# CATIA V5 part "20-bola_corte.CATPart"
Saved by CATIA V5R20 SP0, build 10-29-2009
Part number: 20-bola_corte
Revision: ANY
Definition: UNKNOWN
Nomenclature: 20-bola_corte
Source: Unknown
Bounding box of the stored display mesh (mm): x -2 to 2, y -2 to 2, z -2 to 2
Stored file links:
  C:\Users\Utente\Desktop\IO LAVORO\3D X SITO CF\CUMSA\3D files CX.013058\CX 013058\20-bola_corte.CATPart
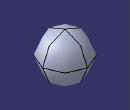
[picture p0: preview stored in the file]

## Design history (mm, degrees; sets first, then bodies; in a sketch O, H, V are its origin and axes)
Body1 "Revolución1" (main body)
  Solid1: solid without history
